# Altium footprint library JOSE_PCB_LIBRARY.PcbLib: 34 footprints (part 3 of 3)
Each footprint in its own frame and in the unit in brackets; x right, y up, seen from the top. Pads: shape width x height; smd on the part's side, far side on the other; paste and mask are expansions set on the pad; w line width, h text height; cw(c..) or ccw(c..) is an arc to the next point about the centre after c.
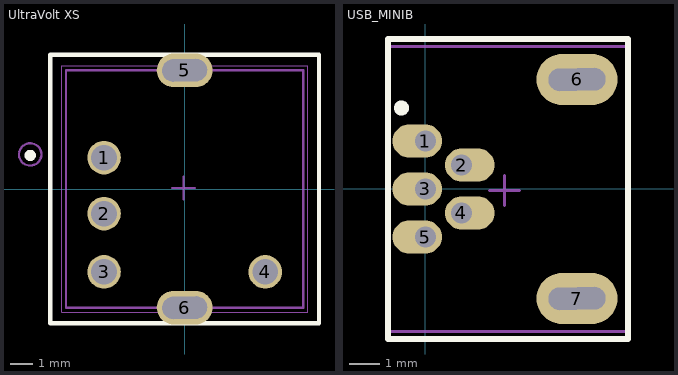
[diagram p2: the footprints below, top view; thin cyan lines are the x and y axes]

## UltraVolt XS [mm] "10.6mmX10.6mm_4pin_UltraVoltXS"
height 11
pads (6):
  round 1.5 hole 1.15: 1(-3.6,1.4) 2(-3.6,-1.1) 3(-3.6,-3.7) 4(3.6,-3.7)
  oval 2.5x1.5 hole 1 slot 2 at 1 deg: 5(0,5.3) 6(0,-5.3)
Top Overlay:
  circle w0.25: c-6.9,1.5 r0.125
  lines w0.2: -6,-6 6,-6 6,6 -6,6 -6,-6
Mechanical 13:
  circle w0.1: c-6.9,1.545 r0.5
  lines w0.1: -5.3,-5.3 -5.3,5.3 5.3,5.3 5.3,-5.3 -5.3,-5.3
Mechanical 15:
  lines w0.05: -5.5,-5.5 5.5,-5.5 5.5,5.5 -5.5,5.5 -5.5,-5.5
  lines w0.1: -0.55,0.045 0.45,0.045 ; -0.05,-0.455 -0.05,0.545
3D body: height 11, standoff 0.1, extent -5.3,-5.3 5.3,5.3
3D body: height 0, standoff -3.5, extent -4.1,0.901 -3.1,1.9
3D body: height 0, standoff -2, extent -0.5,5.05 0.5,5.55
3D body: height 0, standoff -2, extent -0.5,-5.55 0.5,-5.05
3D body: height 0, standoff -3.5, extent -4.1,-1.599 -3.1,-0.6
3D body: height 0, standoff -3.5, extent -4.1,-4.199 -3.1,-3.2
3D body: height 0, standoff -3.5, extent 3.1,-4.199 4.1,-3.2

## USB_MINIB [mm] "USB Mini B"
height 3.95
pads (7):
  oval 1.65x1.1 hole 0.7 copper offset -0.275,0: 1(0,1.6) 3(0,0) 5(0,-1.6)
  oval 1.65x1.1 hole 0.7 copper offset 0.275,0: 2(1.2,0.8) 4(1.2,-0.8)
  oval 2.7x1.7 hole 0.75 slot 1.9 at 1 deg: 6(5.05,3.65) 7(5.05,-3.65)
Top Overlay:
  circle w0.25: c-0.8,2.7 r0.125
  lines w0.2: -1.25,-5 -1.25,5 6.75,5 6.75,-5 -1.25,-5
Bottom Overlay:
  circle w0.25: c-0.8,2.7 r0.125
Mechanical 13:
  lines w0.1: -1.25,-4.75 6.75,-4.75 6.75,4.75 -1.25,4.75 -1.25,-4.75
Mechanical 15:
  lines w0.05: -1.25,-5 -1.25,5 6.75,5 6.75,-5 -1.25,-5
  lines w0.1: 2.134,-0.056 3.134,-0.056 ; 2.634,-0.556 2.634,0.444
3D body "548190519.stp": height 3.95, standoff -1.8, extent -0.2,-3.9 8.8,3.8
